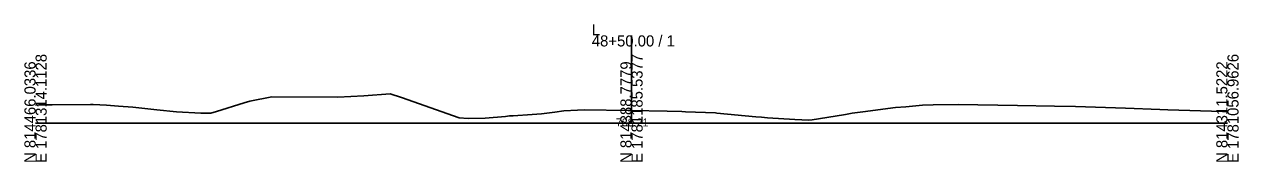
# Model space of a CAD drawing. Extents: x -26 to 7903, y -10 to 9573.
# Drawn here: x 997.2 to 1302.8, y 9490.3 to 9525 of the extents above; entities that cross this region are included whole.
import ezdxf

# ---------------------------------------------------------------- set-up
doc = ezdxf.new("R2010")
doc.units = 0
for name, color, linetype in [('Exist Cross Section Cell', 7, 'Continuous'), ('Exist XS Center Line Elevation Label', 7, 'Continuous'), ('Exist XS Ground Line', 7, 'Continuous')]:
    doc.layers.add(name, color=color, linetype=linetype)

msp = doc.modelspace()

# ---------------------------------------------------------------- linework, layer by layer
at = {"layer": 'Exist Cross Section Cell'}
for p, q in [((1150, 9500), (1150, 9522.17)), ((1000, 9500), (1150, 9500)), ((1150, 9500), (1300, 9500))]:
    msp.add_line(p, q, dxfattribs=at)
at = {"layer": 'Exist XS Ground Line'}
for p, q in [((1076.07, 9506.62), (1082.65, 9506.94)), ((1082.65, 9506.94), (1089.22, 9507.39)), ((1089.22, 9507.39), (1092.13, 9506.5)), ((1000, 9504.6), (1000.85, 9504.62)), ((1000.85, 9504.62), (1002.61, 9504.66)), ((1002.61, 9504.66), (1004.21, 9504.68)), ((1004.21, 9504.68), (1013.85, 9504.77)), ((1013.85, 9504.77), (1014.5, 9504.74)), ((1014.5, 9504.74), (1017.89, 9504.6)), ((1017.89, 9504.6), (1020.91, 9504.31)), ((1020.91, 9504.31), (1024.44, 9504.03)), ((1024.44, 9504.03), (1030.51, 9503.39)), ((1045.52, 9502.94), (1052.51, 9505.14)), ((1052.51, 9505.14), (1053.95, 9505.55)), ((1053.95, 9505.55), (1059.45, 9506.63)), ((1059.45, 9506.63), (1076.07, 9506.62)), ((1092.13, 9506.5), (1106.6, 9501.38)), ((1208.23, 9502.9), (1216.45, 9503.94)), ((1216.45, 9503.94), (1219.05, 9504.17)), ((1219.05, 9504.17), (1223.22, 9504.57)), ((1223.22, 9504.57), (1225.94, 9504.64)), ((1225.94, 9504.64), (1232.2, 9504.75)), ((1232.2, 9504.75), (1247.12, 9504.46)), ((1247.12, 9504.46), (1256.44, 9504.29)), ((1256.44, 9504.29), (1261.76, 9504.2)), ((1261.76, 9504.2), (1274.32, 9503.78)), ((1274.32, 9503.78), (1283, 9503.47)), ((1030.51, 9503.39), (1035.43, 9502.93)), ((1035.43, 9502.93), (1041.59, 9502.55)), ((1041.59, 9502.55), (1044.12, 9502.53)), ((1044.12, 9502.53), (1045.52, 9502.94)), ((1106.6, 9501.38), (1108.91, 9501.21)), ((1108.91, 9501.21), (1113.13, 9501.28)), ((1113.13, 9501.28), (1118.3, 9501.73)), ((1118.3, 9501.73), (1119.25, 9501.86)), ((1119.25, 9501.86), (1120.18, 9501.92)), ((1120.18, 9501.92), (1125, 9502.24)), ((1125, 9502.24), (1127.36, 9502.35)), ((1127.36, 9502.35), (1130.74, 9502.8)), ((1130.74, 9502.8), (1133, 9503.14)), ((1133, 9503.14), (1136.43, 9503.34)), ((1136.43, 9503.34), (1138.14, 9503.41)), ((1138.14, 9503.41), (1149.15, 9503.22)), ((1149.15, 9503.22), (1149.81, 9503.21)), ((1149.81, 9503.21), (1158.98, 9503.02)), ((1158.98, 9503.02), (1162.65, 9502.95)), ((1162.65, 9502.95), (1163.61, 9502.92)), ((1163.61, 9502.92), (1168.63, 9502.73)), ((1168.63, 9502.73), (1171.17, 9502.6)), ((1171.17, 9502.6), (1171.5, 9502.58)), ((1171.5, 9502.58), (1181.31, 9501.62)), ((1181.31, 9501.62), (1182.71, 9501.53)), ((1182.71, 9501.53), (1184.24, 9501.39)), ((1184.24, 9501.39), (1191.13, 9500.99)), ((1191.13, 9500.99), (1194.63, 9500.77)), ((1194.63, 9500.77), (1195.48, 9500.87)), ((1195.48, 9500.87), (1197.11, 9501.16)), ((1197.11, 9501.16), (1203.85, 9502.2)), ((1203.85, 9502.2), (1205.53, 9502.58)), ((1205.53, 9502.58), (1208.23, 9502.9)), ((1283, 9503.47), (1285, 9503.39)), ((1285, 9503.39), (1298.75, 9502.99)), ((1298.75, 9502.99), (1300, 9502.97))]:
    msp.add_line(p, q, dxfattribs=at)

# ---------------------------------------------------------------- texts
at = {"layer": 'Exist Cross Section Cell'}
for s, p in [('48+50.00 / 1', (1140, 9519.37)), ('L', (1140, 9522.17))]:
    msp.add_text(s, height=2.8, dxfattribs=at).set_placement(p)
for s, p in [('E 1781314.1128', (1002.8, 9490)), ('E 1781185.5377', (1152.8, 9490)), ('E 1781056.9626', (1302.8, 9490)), ('N 814466.0336', (1000, 9490)), ('N 814388.7779', (1150, 9490)), ('N 814311.5222', (1300, 9490))]:
    msp.add_text(s, height=2.8, rotation=90, dxfattribs=at).set_placement(p)
at = {"layer": 'Exist XS Center Line Elevation Label'}
msp.add_text('788.21', height=2, dxfattribs=at).set_placement((1146.08, 9499.21))

doc.saveas('drawing.dxf')
